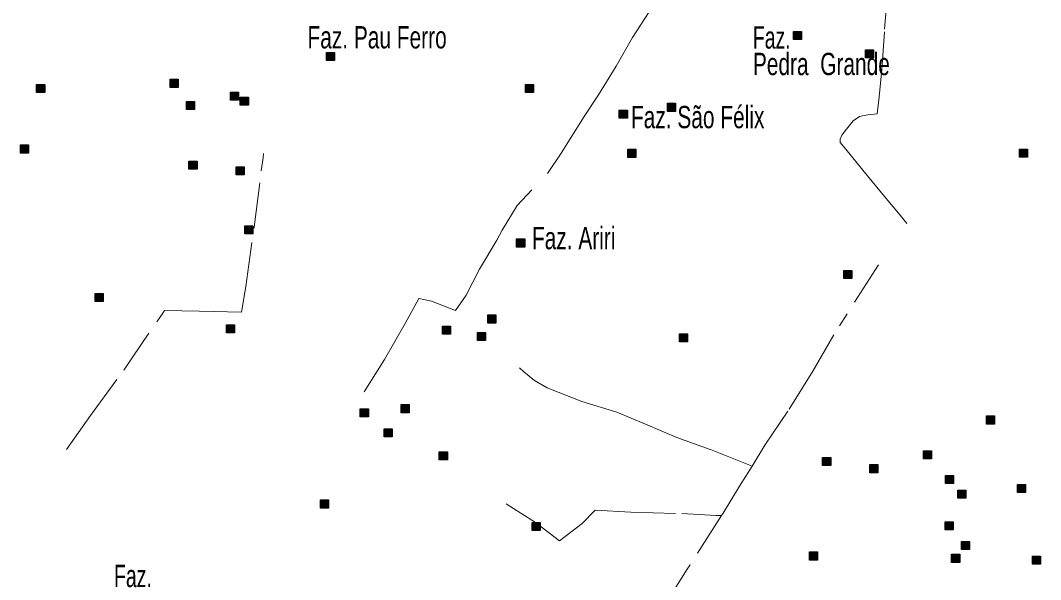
# Model space of a CAD drawing. Extents: x 445.6 to 500, y 8618.1 to 8673.4.
# Drawn here: x 473.35 to 480.67, y 8658.81 to 8662.82 of the extents above; entities that cross this region are included whole.
import ezdxf

# ---------------------------------------------------------------- set-up
doc = ezdxf.new("R2010")
doc.units = 0
doc.header["$LTSCALE"] = 0.064
doc.linetypes.add('DOT_DASHED', pattern=[7.7, 5, -1.2, 0.3, -1.2])
doc.layers.add('2', color=7, linetype='Continuous', lineweight=25)
doc.layers.add('22', color=7, linetype='DOT_DASHED', lineweight=13)
doc.layers.add('61', color=7, linetype='Continuous')

msp = doc.modelspace()

# ---------------------------------------------------------------- hatches: boundary and pattern name
at = {"layer": '2'}
for points in [[(478.897, 8662.7448), (478.955, 8662.7448), (478.955, 8662.6868), (478.897, 8662.6868)], [(475.5478, 8662.5954), (475.6058, 8662.5954), (475.6058, 8662.5374), (475.5478, 8662.5374)], [(479.4134, 8662.6141), (479.4714, 8662.6141), (479.4714, 8662.5561), (479.4134, 8662.5561)], [(473.4689, 8662.365), (473.5269, 8662.365), (473.5269, 8662.307), (473.4689, 8662.307)], [(474.4271, 8662.4023), (474.4851, 8662.4023), (474.4851, 8662.3443), (474.4271, 8662.3443)], [(476.9749, 8662.365), (477.0329, 8662.365), (477.0329, 8662.307), (476.9749, 8662.307)], [(474.8587, 8662.3108), (474.9167, 8662.3108), (474.9167, 8662.2528), (474.8587, 8662.2528)], [(474.9296, 8662.2735), (474.9876, 8662.2735), (474.9876, 8662.2155), (474.9296, 8662.2155)], [(474.5436, 8662.2431), (474.6016, 8662.2431), (474.6016, 8662.1851), (474.5436, 8662.1851)], [(477.9939, 8662.2298), (478.0519, 8662.2298), (478.0519, 8662.1718), (477.9939, 8662.1718)], [(477.6483, 8662.1813), (477.7063, 8662.1813), (477.7063, 8662.1233), (477.6483, 8662.1233)], [(473.3525, 8661.9307), (473.4105, 8661.9307), (473.4105, 8661.8727), (473.3525, 8661.8727)], [(477.7091, 8661.9001), (477.7671, 8661.9001), (477.7671, 8661.8421), (477.7091, 8661.8421)], [(480.5192, 8661.9002), (480.5772, 8661.9002), (480.5772, 8661.8422), (480.5192, 8661.8422)], [(474.5617, 8661.8155), (474.6197, 8661.8155), (474.6197, 8661.7575), (474.5617, 8661.7575)], [(474.8995, 8661.7749), (474.9575, 8661.7749), (474.9575, 8661.7169), (474.8995, 8661.7169)], [(474.9617, 8661.3515), (475.0197, 8661.3515), (475.0197, 8661.2935), (474.9617, 8661.2935)], [(476.912, 8661.2564), (476.97, 8661.2564), (476.97, 8661.1984), (476.912, 8661.1984)], [(479.2581, 8661.0294), (479.3161, 8661.0294), (479.3161, 8660.9714), (479.2581, 8660.9714)], [(473.8892, 8660.8659), (473.9472, 8660.8659), (473.9472, 8660.8079), (473.8892, 8660.8079)], [(476.7059, 8660.711), (476.7639, 8660.711), (476.7639, 8660.653), (476.7059, 8660.653)], [(474.8299, 8660.64), (474.8879, 8660.64), (474.8879, 8660.582), (474.8299, 8660.582)], [(476.3797, 8660.6301), (476.4377, 8660.6301), (476.4377, 8660.5721), (476.3797, 8660.5721)], [(476.6316, 8660.5856), (476.6896, 8660.5856), (476.6896, 8660.5276), (476.6316, 8660.5276)], [(478.0798, 8660.5756), (478.1378, 8660.5756), (478.1378, 8660.5176), (478.0798, 8660.5176)], [(475.7908, 8660.0371), (475.8488, 8660.0371), (475.8488, 8659.9791), (475.7908, 8659.9791)], [(476.0831, 8660.0675), (476.1411, 8660.0675), (476.1411, 8660.0095), (476.0831, 8660.0095)], [(480.2814, 8659.9858), (480.3394, 8659.9858), (480.3394, 8659.9278), (480.2814, 8659.9278)], [(475.962, 8659.8946), (476.02, 8659.8946), (476.02, 8659.8366), (475.962, 8659.8366)], [(476.3572, 8659.7286), (476.4152, 8659.7286), (476.4152, 8659.6706), (476.3572, 8659.6706)], [(479.8298, 8659.7354), (479.8878, 8659.7354), (479.8878, 8659.6774), (479.8298, 8659.6774)], [(479.107, 8659.6879), (479.165, 8659.6879), (479.165, 8659.6299), (479.107, 8659.6299)], [(479.4447, 8659.6371), (479.5027, 8659.6371), (479.5027, 8659.5791), (479.4447, 8659.5791)], [(479.9886, 8659.5592), (480.0466, 8659.5592), (480.0466, 8659.5012), (479.9886, 8659.5012)], [(480.5043, 8659.4945), (480.5623, 8659.4945), (480.5623, 8659.4365), (480.5043, 8659.4365)], [(480.0764, 8659.4542), (480.1344, 8659.4542), (480.1344, 8659.3962), (480.0764, 8659.3962)], [(475.5041, 8659.383), (475.5621, 8659.383), (475.5621, 8659.325), (475.5041, 8659.325)], [(477.0224, 8659.2226), (477.0804, 8659.2226), (477.0804, 8659.1646), (477.0224, 8659.1646)], [(479.9852, 8659.2272), (480.0432, 8659.2272), (480.0432, 8659.1692), (479.9852, 8659.1692)], [(480.1034, 8659.0849), (480.1614, 8659.0849), (480.1614, 8659.0269), (480.1034, 8659.0269)], [(479.0124, 8659.0103), (479.0704, 8659.0103), (479.0704, 8658.9523), (479.0124, 8658.9523)], [(480.0325, 8658.9934), (480.0905, 8658.9934), (480.0905, 8658.9354), (480.0325, 8658.9354)], [(480.6124, 8658.9795), (480.6704, 8658.9795), (480.6704, 8658.9215), (480.6124, 8658.9215)]]:
    msp.add_hatch(color=256, dxfattribs=at).paths.add_polyline_path(points)

# ---------------------------------------------------------------- linework, layer by layer
for points in [[(478.897, 8662.7448), (478.955, 8662.7448), (478.955, 8662.6868), (478.897, 8662.6868)], [(475.5478, 8662.5954), (475.6058, 8662.5954), (475.6058, 8662.5374), (475.5478, 8662.5374)], [(479.4134, 8662.6141), (479.4714, 8662.6141), (479.4714, 8662.5561), (479.4134, 8662.5561)], [(473.4689, 8662.365), (473.5269, 8662.365), (473.5269, 8662.307), (473.4689, 8662.307)], [(474.4271, 8662.4023), (474.4851, 8662.4023), (474.4851, 8662.3443), (474.4271, 8662.3443)], [(476.9749, 8662.365), (477.0329, 8662.365), (477.0329, 8662.307), (476.9749, 8662.307)], [(474.8587, 8662.3108), (474.9167, 8662.3108), (474.9167, 8662.2528), (474.8587, 8662.2528)], [(474.9296, 8662.2735), (474.9876, 8662.2735), (474.9876, 8662.2155), (474.9296, 8662.2155)], [(474.5436, 8662.2431), (474.6016, 8662.2431), (474.6016, 8662.1851), (474.5436, 8662.1851)], [(477.9939, 8662.2298), (478.0519, 8662.2298), (478.0519, 8662.1718), (477.9939, 8662.1718)], [(477.6483, 8662.1813), (477.7063, 8662.1813), (477.7063, 8662.1233), (477.6483, 8662.1233)], [(473.3525, 8661.9307), (473.4105, 8661.9307), (473.4105, 8661.8727), (473.3525, 8661.8727)], [(477.7091, 8661.9001), (477.7671, 8661.9001), (477.7671, 8661.8421), (477.7091, 8661.8421)], [(480.5192, 8661.9002), (480.5772, 8661.9002), (480.5772, 8661.8422), (480.5192, 8661.8422)], [(474.5617, 8661.8155), (474.6197, 8661.8155), (474.6197, 8661.7575), (474.5617, 8661.7575)], [(474.8995, 8661.7749), (474.9575, 8661.7749), (474.9575, 8661.7169), (474.8995, 8661.7169)], [(474.9617, 8661.3515), (475.0197, 8661.3515), (475.0197, 8661.2935), (474.9617, 8661.2935)], [(476.912, 8661.2564), (476.97, 8661.2564), (476.97, 8661.1984), (476.912, 8661.1984)], [(479.2581, 8661.0294), (479.3161, 8661.0294), (479.3161, 8660.9714), (479.2581, 8660.9714)], [(473.8892, 8660.8659), (473.9472, 8660.8659), (473.9472, 8660.8079), (473.8892, 8660.8079)], [(476.7059, 8660.711), (476.7639, 8660.711), (476.7639, 8660.653), (476.7059, 8660.653)], [(474.8299, 8660.64), (474.8879, 8660.64), (474.8879, 8660.582), (474.8299, 8660.582)], [(476.3797, 8660.6301), (476.4377, 8660.6301), (476.4377, 8660.5721), (476.3797, 8660.5721)], [(476.6316, 8660.5856), (476.6896, 8660.5856), (476.6896, 8660.5276), (476.6316, 8660.5276)], [(478.0798, 8660.5756), (478.1378, 8660.5756), (478.1378, 8660.5176), (478.0798, 8660.5176)], [(475.7908, 8660.0371), (475.8488, 8660.0371), (475.8488, 8659.9791), (475.7908, 8659.9791)], [(476.0831, 8660.0675), (476.1411, 8660.0675), (476.1411, 8660.0095), (476.0831, 8660.0095)], [(480.2814, 8659.9858), (480.3394, 8659.9858), (480.3394, 8659.9278), (480.2814, 8659.9278)], [(475.962, 8659.8946), (476.02, 8659.8946), (476.02, 8659.8366), (475.962, 8659.8366)], [(476.3572, 8659.7286), (476.4152, 8659.7286), (476.4152, 8659.6706), (476.3572, 8659.6706)], [(479.8298, 8659.7354), (479.8878, 8659.7354), (479.8878, 8659.6774), (479.8298, 8659.6774)], [(479.107, 8659.6879), (479.165, 8659.6879), (479.165, 8659.6299), (479.107, 8659.6299)], [(479.4447, 8659.6371), (479.5027, 8659.6371), (479.5027, 8659.5791), (479.4447, 8659.5791)], [(479.9886, 8659.5592), (480.0466, 8659.5592), (480.0466, 8659.5012), (479.9886, 8659.5012)], [(480.5043, 8659.4945), (480.5623, 8659.4945), (480.5623, 8659.4365), (480.5043, 8659.4365)], [(480.0764, 8659.4542), (480.1344, 8659.4542), (480.1344, 8659.3962), (480.0764, 8659.3962)], [(475.5041, 8659.383), (475.5621, 8659.383), (475.5621, 8659.325), (475.5041, 8659.325)], [(477.0224, 8659.2226), (477.0804, 8659.2226), (477.0804, 8659.1646), (477.0224, 8659.1646)], [(479.9852, 8659.2272), (480.0432, 8659.2272), (480.0432, 8659.1692), (479.9852, 8659.1692)], [(480.1034, 8659.0849), (480.1614, 8659.0849), (480.1614, 8659.0269), (480.1034, 8659.0269)], [(479.0124, 8659.0103), (479.0704, 8659.0103), (479.0704, 8658.9523), (479.0124, 8658.9523)], [(480.0325, 8658.9934), (480.0905, 8658.9934), (480.0905, 8658.9354), (480.0325, 8658.9354)], [(480.6124, 8658.9795), (480.6704, 8658.9795), (480.6704, 8658.9215), (480.6124, 8658.9215)]]:
    msp.add_lwpolyline(points, close=True, dxfattribs=at)
at = {"layer": '22'}
for points in [[(477.1332, 8661.7261), (477.231, 8661.8711), (477.3958, 8662.136), (477.4999, 8662.291), (477.6256, 8662.4974), (477.7429, 8662.701), (477.8323, 8662.8376), (478.0451, 8663.1769), (478.2745, 8663.6052), (478.3918, 8663.8004), (478.5314, 8664.0765), (478.7189, 8664.4018), (478.8725, 8664.6806), (479.0683, 8665.0391), (479.1117, 8665.1297)], [(479.6686, 8664.3706), (479.6498, 8664.1432), (479.6224, 8663.6978), (479.5973, 8663.3548), (479.5775, 8663.0797), (479.5496, 8662.7423), (479.5326, 8662.4729), (479.5128, 8662.2765), (479.4988, 8662.1538), (479.4318, 8662.1482), (479.4039, 8662.1426), (479.3704, 8662.1343), (479.3257, 8662.1036), (479.2782, 8662.045), (479.2447, 8662.0004), (479.2335, 8661.9725), (479.2335, 8661.9474), (479.2726, 8661.9), (479.3955, 8661.7494), (479.5634, 8661.5475), (479.664, 8661.4276), (479.712, 8661.3675)], [(473.6837, 8659.7465), (473.8549, 8659.9899), (474.0939, 8660.3148), (474.3736, 8660.7246), (474.3851, 8660.7418), (474.6357, 8660.739), (474.938, 8660.7303), (474.9697, 8660.9144), (475.0281, 8661.3418), (475.0801, 8661.7455), (475.0945, 8661.8375), (475.0968, 8661.8706)], [(475.819, 8660.1587), (475.965, 8660.3919), (476.113, 8660.6485), (476.211, 8660.8284), (476.3004, 8660.8089), (476.4735, 8660.7419), (476.5489, 8660.8535), (476.6467, 8661.0403), (476.7695, 8661.2467), (476.8086, 8661.3192), (476.9154, 8661.4974), (477.0215, 8661.609)], [(479.5087, 8661.0717), (479.1862, 8660.5685), (479.0365, 8660.3069), (478.8573, 8660.0204), (478.6932, 8659.776), (478.6007, 8659.6261)], [(478.6007, 8659.6261), (478.301, 8659.7453), (478.06, 8659.8323), (477.8365, 8659.928), (477.6303, 8660.0121), (477.3806, 8660.0903), (477.1299, 8660.1875), (477.0398, 8660.2397), (476.9644, 8660.3035), (476.9324, 8660.3325)], [(478.6007, 8659.6261), (478.5112, 8659.4811), (478.3932, 8659.2885), (478.3826, 8659.2719)], [(476.837, 8659.3556), (477.0476, 8659.2224), (477.2197, 8659.0891), (477.3812, 8659.2153), (477.476, 8659.31), (477.7323, 8659.296), (478.0974, 8659.2855), (478.3397, 8659.2714), (478.3826, 8659.2719)], [(478.3826, 8659.2719), (478.1362, 8658.8873), (478.0066, 8658.6797)]]:
    msp.add_lwpolyline(points, dxfattribs=at)

# ---------------------------------------------------------------- texts
at = {"layer": '61'}
for s, width, p in [('Faz. Pau Ferro', 0.7, (475.4116, 8662.6238)), ('Faz.', 0.65, (478.6067, 8662.6222)), ('Pedra  Grande', 0.7, (478.6067, 8662.4322)), ('Faz. São Félix', 0.7, (477.732, 8662.0511)), ('Faz. Ariri', 0.7, (477.0218, 8661.1825)), ('Faz.', 0.65, (474.0245, 8658.7578))]:
    msp.add_text(s, height=0.16, dxfattribs=dict(at, width=width)).set_placement(p)

doc.saveas('drawing.dxf')
